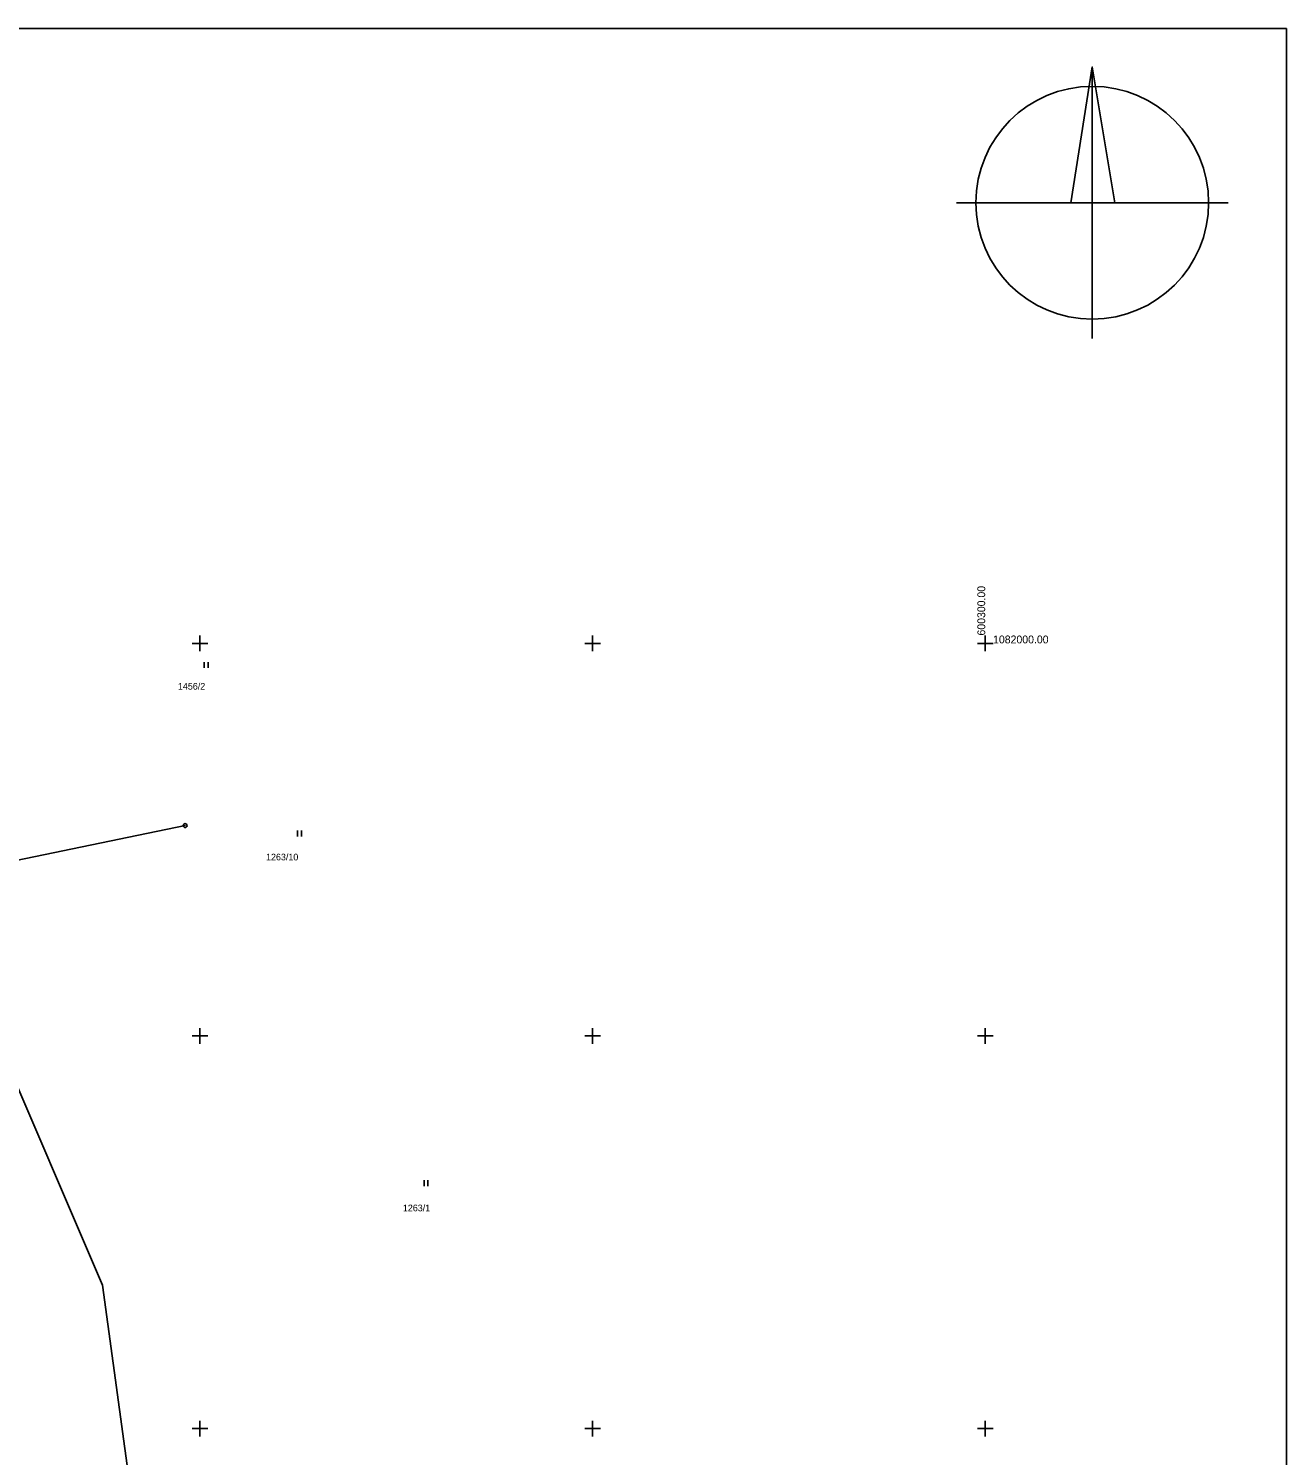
# Model space of a CAD drawing. Extents: x -601196 to -600262, y -1082523 to -1081922.
# Drawn here: x -600421.8 to -600261.6, y -1082103.4 to -1081921.7 of the extents above; entities that cross this region are included whole.
import ezdxf

# ---------------------------------------------------------------- set-up
doc = ezdxf.new("R2010")
doc.units = 0
for name, color, linetype in [('Vrstva 47', 7, 'Continuous'), ('Vrstva 59', 7, 'Continuous'), ('Vrstva 60', 7, 'Continuous'), ('Vrstva 61', 7, 'Continuous'), ('Vrstva 63', 7, 'Continuous')]:
    doc.layers.add(name, color=color, linetype=linetype)

msp = doc.modelspace()

# ---------------------------------------------------------------- linework, layer by layer
at = {"layer": 'Vrstva 47'}
for p, q in [((-600399.48, -1082003.13), (-600399.48, -1082002.38)), ((-600398.98, -1082002.38), (-600398.98, -1082003.13)), ((-600433.64, -1082029.76), (-600401.89, -1082023.21)), ((-600387.57, -1082024.6), (-600387.57, -1082023.85)), ((-600387.07, -1082023.85), (-600387.07, -1082024.6)), ((-600427.7, -1082046.11), (-600412.41, -1082081.75)), ((-600371.47, -1082069.12), (-600371.47, -1082068.37)), ((-600370.97, -1082068.37), (-600370.97, -1082069.12)), ((-600412.41, -1082081.75), (-600407.06, -1082120.94))]:
    msp.add_line(p, q, dxfattribs=at)
for radius in [0.25, 0.005]:
    msp.add_circle((-600401.89, -1082023.21), radius, dxfattribs=at)
at = {"layer": 'Vrstva 59'}
msp.add_lwpolyline([(-600681.64, -1082515.69), (-600681.64, -1081921.69), (-600261.64, -1081921.69), (-600261.64, -1082515.69)], close=True, dxfattribs=at)
at = {"layer": 'Vrstva 60'}
for p, q in [((-600289.1, -1081943.88), (-600286.37, -1081926.59)), ((-600286.37, -1081961.17), (-600286.37, -1081926.59)), ((-600303.65, -1081943.88), (-600269.08, -1081943.88))]:
    msp.add_line(p, q, dxfattribs=at)
msp.add_lwpolyline([(-600283.51, -1081943.88), (-600286.37, -1081926.59), (-600286.37, -1081943.88)], close=True, dxfattribs=at)
msp.add_circle((-600286.37, -1081943.88), 14.82, dxfattribs=at)
at = {"layer": 'Vrstva 61'}
for p, q in [((-600400, -1081999), (-600400, -1082001)), ((-600350, -1081999), (-600350, -1082001)), ((-600300, -1081999), (-600300, -1082001)), ((-600401, -1082000), (-600399, -1082000)), ((-600351, -1082000), (-600349, -1082000)), ((-600301, -1082000), (-600299, -1082000)), ((-600401, -1082050), (-600399, -1082050)), ((-600401, -1082050), (-600399, -1082050)), ((-600400, -1082049), (-600400, -1082051)), ((-600400, -1082049), (-600400, -1082051)), ((-600351, -1082050), (-600349, -1082050)), ((-600351, -1082050), (-600349, -1082050)), ((-600350, -1082049), (-600350, -1082051)), ((-600350, -1082049), (-600350, -1082051)), ((-600301, -1082050), (-600299, -1082050)), ((-600301, -1082050), (-600299, -1082050)), ((-600300, -1082049), (-600300, -1082051)), ((-600300, -1082049), (-600300, -1082051)), ((-600400, -1082099), (-600400, -1082101)), ((-600400, -1082099), (-600400, -1082101)), ((-600350, -1082099), (-600350, -1082101)), ((-600350, -1082099), (-600350, -1082101)), ((-600300, -1082099), (-600300, -1082101)), ((-600300, -1082099), (-600300, -1082101)), ((-600401, -1082100), (-600399, -1082100)), ((-600401, -1082100), (-600399, -1082100)), ((-600351, -1082100), (-600349, -1082100)), ((-600351, -1082100), (-600349, -1082100)), ((-600301, -1082100), (-600299, -1082100)), ((-600301, -1082100), (-600299, -1082100))]:
    msp.add_line(p, q, dxfattribs=at)

# ---------------------------------------------------------------- texts
at = {"layer": 'Vrstva 47'}
for s, p in [('1456/2', (-600402.81, -1082005.89)), ('1263/10', (-600391.59, -1082027.64)), ('1263/1', (-600374.16, -1082072.33))]:
    msp.add_text(s, height=0.85, dxfattribs=at).set_placement(p)
at = {"layer": 'Vrstva 63'}
msp.add_text('600300.00', height=1, rotation=90, dxfattribs=at).set_placement((-600300, -1081999))
msp.add_text('1082000.00', height=1, dxfattribs=at).set_placement((-600299, -1082000))

doc.saveas('drawing.dxf')
